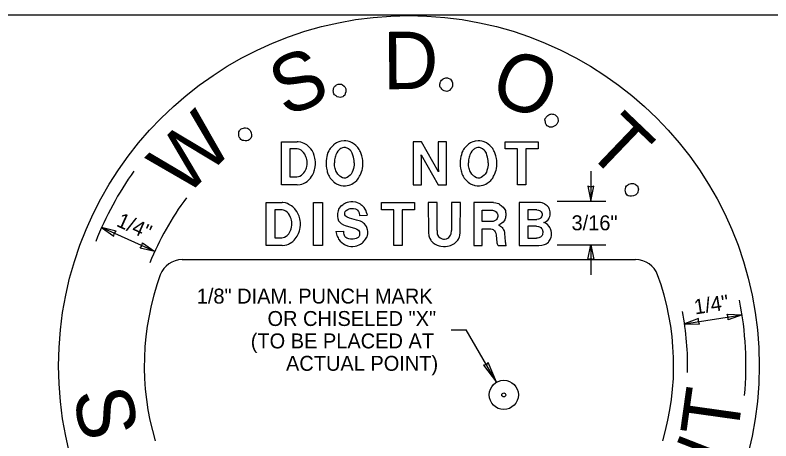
# Model space of a CAD drawing. Extents: x 99862 to 103151, y 100000 to 102076.
# Drawn here: x 100680 to 101489, y 101619 to 102076 of the extents above; entities that cross this region are included whole.
import ezdxf

# ---------------------------------------------------------------- set-up
doc = ezdxf.new("R2010")
doc.units = 0
for name, color, linetype in [('Level 1', 7, 'Continuous'), ('Level 10', 7, 'Continuous'), ('Level 15', 7, 'Continuous'), ('Level 18', 7, 'Continuous'), ('Level 20', 7, 'Continuous'), ('Level 6', 7, 'Continuous')]:
    doc.layers.add(name, color=color, linetype=linetype)

msp = doc.modelspace()

# ---------------------------------------------------------------- linework, layer by layer
at = {"layer": 'Level 1'}
msp.add_lwpolyline([(99862, 99999.5), (103151, 99999.5), (103151, 102075.5), (99862, 102075.5)], close=True, dxfattribs=at)
for radius, start, end in [(360.73, 144.68888, 158.35001), (298.33, 142.94323, 158.35001), (360.73, 354.93234, 11.21108), (298.33, 358.58596, 11.21108)]:
    msp.add_arc((101101.53, 101700), radius, start, end, dxfattribs=at)
at = {"layer": 'Level 10'}
for points in [[(101135.9, 101997.37), (101135.51, 101997.93), (101135.12, 101998.49), (101134.72, 101999.06), (101134.51, 102000.57), (101134.69, 102001.53), (101134.86, 102002.47), (101135.04, 102003.43), (101135.77, 102004.77), (101136.43, 102005.64), (101137.64, 102006.89), (101138.21, 102007.28), (101138.77, 102007.67), (101139.81, 102007.97), (101140.85, 102008.27), (101142.84, 102008.4), (101146.01, 102006.83), (101146.78, 102005.71), (101147.95, 102004.02), (101148.24, 102002.98), (101148.29, 102000.51), (101148.11, 101999.55), (101147.28, 101997.74), (101145.99, 101996), (101144.76, 101994.75), (101143.17, 101994.06), (101142.12, 101993.76), (101140.69, 101994.02), (101139.27, 101994.28), (101137.93, 101995.03), (101136.67, 101996.23), (101135.9, 101997.37)], [(101023.54, 101988.86), (101022.97, 101989.24), (101022.4, 101989.61), (101021.82, 101989.99), (101021.06, 101991.31), (101020.86, 101992.26), (101020.66, 101993.2), (101020.46, 101994.16), (101020.64, 101995.68), (101020.92, 101996.72), (101021.57, 101998.35), (101021.95, 101998.92), (101022.33, 101999.49), (101023.18, 102000.16), (101024.03, 102000.82), (101025.82, 102001.7), (101029.34, 102001.44), (101030.48, 102000.68), (101032.2, 101999.56), (101032.87, 101998.71), (101033.84, 101996.44), (101034.04, 101995.49), (101033.95, 101993.49), (101033.4, 101991.4), (101032.75, 101989.78), (101031.52, 101988.54), (101030.67, 101987.87), (101029.25, 101987.57), (101027.83, 101987.28), (101026.31, 101987.46), (101024.69, 101988.1), (101023.54, 101988.86)], [(101247.58, 101961.12), (101247.43, 101961.78), (101247.28, 101962.45), (101247.13, 101963.12), (101247.5, 101964.6), (101248.03, 101965.42), (101248.55, 101966.23), (101249.07, 101967.06), (101250.26, 101968.02), (101251.19, 101968.57), (101252.79, 101969.28), (101253.46, 101969.42), (101254.12, 101969.58), (101255.2, 101969.46), (101256.27, 101969.35), (101258.17, 101968.71), (101260.51, 101966.07), (101260.8, 101964.74), (101261.25, 101962.74), (101261.13, 101961.66), (101260.24, 101959.35), (101259.72, 101958.54), (101258.27, 101957.17), (101256.41, 101956.05), (101254.81, 101955.35), (101253.07, 101955.32), (101251.99, 101955.43), (101250.76, 101956.21), (101249.54, 101956.99), (101248.58, 101958.18), (101247.87, 101959.77), (101247.58, 101961.12)], [(100924.75, 101941.07), (100924.08, 101941.2), (100923.41, 101941.33), (100922.73, 101941.46), (100921.53, 101942.4), (100920.98, 101943.21), (100920.45, 101944.01), (100919.9, 101944.82), (100919.49, 101946.29), (100919.36, 101947.37), (100919.35, 101949.11), (100919.49, 101949.79), (100919.62, 101950.46), (100920.15, 101951.4), (100920.69, 101952.34), (100922.03, 101953.82), (100925.38, 101954.91), (100926.72, 101954.64), (100928.74, 101954.24), (100929.68, 101953.71), (100931.43, 101951.97), (100931.97, 101951.16), (100932.65, 101949.28), (100932.93, 101947.14), (100932.93, 101945.39), (100932.26, 101943.78), (100931.73, 101942.84), (100930.52, 101942.02), (100929.32, 101941.22), (100927.84, 101940.82), (100926.1, 101940.8), (100924.75, 101941.07)], [(101333.33, 101889.49), (101333.44, 101890.15), (101333.55, 101890.83), (101333.67, 101891.51), (101334.57, 101892.74), (101335.37, 101893.31), (101336.15, 101893.86), (101336.95, 101894.43), (101338.41, 101894.87), (101339.48, 101895.03), (101341.23, 101895.09), (101341.9, 101894.97), (101342.58, 101894.86), (101343.53, 101894.34), (101344.48, 101893.83), (101346, 101892.53), (101347.17, 101889.21), (101346.94, 101887.86), (101346.6, 101885.84), (101346.09, 101884.88), (101344.39, 101883.08), (101343.6, 101882.52), (101341.74, 101881.8), (101339.6, 101881.46), (101337.85, 101881.42), (101336.23, 101882.04), (101335.27, 101882.55), (101334.43, 101883.74), (101333.59, 101884.92), (101333.15, 101886.39), (101333.09, 101888.13), (101333.33, 101889.49)]]:
    msp.add_lwpolyline(points, dxfattribs=at)
at = {"layer": 'Level 15'}
for p, q in [((101296.23, 101908.37), (101296.23, 101876.37)), ((101260.23, 101876.37), (101312.23, 101876.37)), ((100829.4, 101822.25), (100772.48, 101847.82)), ((101260.23, 101829.44), (101312.23, 101829.44)), ((101296.23, 101829.44), (101296.23, 101797.44)), ((101396.45, 101744.97), (101458.15, 101754.38)), ((101146.74, 101738.51), (101162.74, 101738.51)), ((101195.24, 101682.22), (101162.74, 101738.51))]:
    msp.add_line(p, q, dxfattribs=at)
for points in [[(101296.23, 101876.37), (101299.32, 101892.1), (101296.23, 101891.37), (101293.15, 101892.1)], [(100772.48, 101847.82), (100785.56, 101838.57), (100786.16, 101841.68), (100788.08, 101844.19)], [(100829.4, 101822.25), (100813.79, 101825.88), (100815.72, 101828.4), (100816.32, 101831.51)], [(101296.23, 101829.44), (101299.32, 101813.72), (101296.23, 101814.45), (101293.15, 101813.72)], [(101396.45, 101744.97), (101412.46, 101744.29), (101411.28, 101747.23), (101411.53, 101750.39)], [(101458.15, 101754.38), (101443.07, 101748.96), (101443.32, 101752.12), (101442.14, 101755.06)], [(101195.25, 101682.22), (101186.42, 101703.48), (101184.36, 101701.07), (101181.25, 101700.5)]]:
    msp.add_lwpolyline(points, close=True, dxfattribs=at)
at = {"layer": 'Level 18'}
msp.add_line((100858.88, 101813.63), (101344.18, 101813.63), dxfattribs=at)
for centre, radius, start, end in [((100858.88, 101788.63), 25, 90, 159.93574), ((101344.18, 101788.63), 25, 20.06426, 90), ((101101.53, 101700), 283.33, 159.93574, 196.52295), ((101101.53, 101700), 283.33, 343.47705, 20.06426)]:
    msp.add_arc(centre, radius, start, end, dxfattribs=at)
at = {"layer": 'Level 20'}
for points in [[(100981.97, 101893.76), (100965.04, 101893.76), (100965.04, 101939.76), (100981.97, 101939.76)], [(100981.97, 101893.76), (100985.02, 101894.13), (100987.05, 101894.49), (100988.74, 101895.21), (100990.1, 101895.94), (100990.77, 101896.29), (100992.47, 101897.39), (100993.48, 101898.11), (100994.83, 101899.56), (100996.19, 101901.01), (100997.21, 101902.46), (100998.23, 101903.9), (100998.9, 101905.35), (100999.57, 101906.8), (101000.25, 101908.61), (101000.59, 101909.71), (101000.93, 101911.15), (101001.27, 101912.96), (101001.61, 101915.49), (101001.61, 101916.94), (101001.61, 101918.39), (101001.27, 101920.57), (101000.93, 101922.37), (101000.59, 101923.82), (101000.25, 101925.28), (100999.24, 101927.45), (100998.56, 101928.9), (100997.88, 101930.35), (100996.53, 101932.15), (100995.52, 101933.24), (100994.5, 101934.33), (100993.48, 101935.42), (100992.13, 101936.5), (100990.77, 101937.23), (100989.42, 101937.95), (100987.73, 101938.68), (100985.7, 101939.4), (100982.99, 101939.76), (100981.97, 101939.76)], [(101032.46, 101940.85), (101029.08, 101940.49), (101027.72, 101940.13), (101026.36, 101939.76), (101024.67, 101939.04), (101023.99, 101938.68), (101022.98, 101937.95), (101021.96, 101937.23), (101020.95, 101936.5), (101020.61, 101936.14), (101018.24, 101933.6), (101017.22, 101932.52), (101016.54, 101931.43), (101015.87, 101929.98), (101014.85, 101928.17), (101014.17, 101926), (101013.5, 101924.19), (101013.16, 101922.02), (101012.82, 101919.48), (101012.82, 101917.67), (101012.82, 101916.58)], [(101052.1, 101916.58), (101052.1, 101918.76), (101052.1, 101919.84), (101051.76, 101922.02), (101051.42, 101923.47), (101051.08, 101924.92), (101050.4, 101927.08), (101049.73, 101928.9), (101049.05, 101929.98), (101048.37, 101931.43), (101047.7, 101932.52), (101046.68, 101933.6), (101044.65, 101935.78), (101042.96, 101937.23), (101040.92, 101938.68), (101038.55, 101939.76), (101037.54, 101940.13), (101036.18, 101940.49), (101033.81, 101940.85), (101032.12, 101940.85)], [(101106.18, 101939.76), (101106.18, 101893.76), (101114.98, 101893.76), (101114.98, 101922.37), (101114.64, 101926), (101132.92, 101893.76), (101141.73, 101893.76), (101141.73, 101939.76), (101132.92, 101939.76), (101132.92, 101912.6), (101133.26, 101907.53), (101114.98, 101939.76), (101106.18, 101939.76)], [(101175.92, 101940.85), (101172.54, 101940.49), (101171.19, 101940.13), (101169.83, 101939.76), (101168.14, 101939.04), (101167.45, 101938.68), (101166.44, 101937.95), (101165.43, 101937.23), (101164.41, 101936.5), (101164.07, 101936.14), (101161.7, 101933.6), (101160.69, 101932.52), (101160, 101931.43), (101159.33, 101929.98), (101158.31, 101928.17), (101157.64, 101926), (101156.96, 101924.19), (101156.62, 101922.02), (101156.28, 101919.48), (101156.28, 101917.67), (101156.28, 101916.58)], [(101195.56, 101916.58), (101195.56, 101918.76), (101195.56, 101919.84), (101195.22, 101922.02), (101194.88, 101923.47), (101194.54, 101924.92), (101193.87, 101927.08), (101193.19, 101928.9), (101192.51, 101929.98), (101191.83, 101931.43), (101191.16, 101932.52), (101190.14, 101933.6), (101188.11, 101935.78), (101186.42, 101937.23), (101184.38, 101938.68), (101182.01, 101939.76), (101181, 101940.13), (101179.65, 101940.49), (101177.27, 101940.85), (101175.58, 101940.85)], [(101204.45, 101939.76), (101240, 101939.76), (101240, 101932.15), (101226.8, 101932.15), (101226.8, 101893.76), (101217.66, 101893.76), (101217.66, 101932.15), (101204.45, 101932.15), (101204.45, 101939.76)], [(100981.63, 101932.15), (100974.19, 101932.15), (100974.19, 101902.1), (100981.63, 101902.1)], [(100981.63, 101902.1), (100983.32, 101902.46), (100984.68, 101902.82), (100986.37, 101903.9), (100987.39, 101904.63), (100988.06, 101905.35), (100989.08, 101906.44), (100990.1, 101907.89), (100990.77, 101909.34), (100991.45, 101910.79), (100991.79, 101911.87), (100992.13, 101913.32), (100992.47, 101915.49), (100992.47, 101916.94), (100992.47, 101919.12), (100992.13, 101920.93), (100991.79, 101922.37), (100991.11, 101923.82), (100990.1, 101926.37), (100988.74, 101928.17), (100987.39, 101929.62), (100986.03, 101930.71), (100984.68, 101931.43), (100983.67, 101931.79), (100981.97, 101932.15), (100981.63, 101932.15)], [(101042.96, 101917.31), (101042.96, 101918.03), (101042.96, 101919.84), (101042.61, 101921.65), (101042.28, 101923.47), (101041.6, 101925.64), (101040.92, 101927.45), (101039.56, 101929.62), (101038.55, 101930.71), (101036.86, 101932.15), (101035.51, 101932.88), (101034.49, 101933.24), (101033.48, 101933.6), (101032.8, 101933.6), (101031.78, 101933.6), (101030.43, 101933.24), (101028.74, 101932.52), (101027.72, 101931.79), (101027.04, 101931.43), (101026.36, 101930.71), (101025.69, 101929.98), (101025.34, 101929.62), (101024.33, 101927.81), (101023.32, 101926), (101022.98, 101924.55), (101022.64, 101923.47), (101022.3, 101922.02), (101021.96, 101920.57), (101021.96, 101919.48), (101021.96, 101918.03), (101021.96, 101917.31)], [(101186.42, 101917.31), (101186.42, 101918.03), (101186.42, 101919.84), (101186.08, 101921.65), (101185.74, 101923.47), (101185.06, 101925.64), (101184.38, 101927.45), (101183.03, 101929.62), (101182.01, 101930.71), (101180.32, 101932.15), (101178.97, 101932.88), (101177.95, 101933.24), (101176.94, 101933.6), (101176.26, 101933.6), (101175.24, 101933.6), (101173.89, 101933.24), (101172.2, 101932.52), (101171.19, 101931.79), (101170.5, 101931.43), (101169.83, 101930.71), (101169.15, 101929.98), (101168.81, 101929.62), (101167.79, 101927.81), (101166.78, 101926), (101166.44, 101924.55), (101166.1, 101923.47), (101165.76, 101922.02), (101165.43, 101920.57), (101165.43, 101919.48), (101165.43, 101918.03), (101165.43, 101917.31)], [(101012.82, 101916.58), (101012.82, 101915.49), (101012.82, 101913.69), (101013.16, 101911.51), (101013.5, 101910.06), (101013.83, 101908.61), (101014.17, 101907.53), (101014.85, 101905.35), (101015.53, 101903.9), (101016.21, 101902.82), (101017.22, 101901.01), (101017.9, 101900.28), (101020.61, 101897.39), (101021.29, 101896.66), (101022.98, 101895.58), (101023.99, 101894.85), (101024.67, 101894.49), (101025.69, 101894.13), (101026.36, 101893.76), (101027.72, 101893.4), (101028.74, 101893.04), (101031.1, 101892.68), (101032.8, 101892.68), (101033.48, 101892.68), (101035.51, 101893.04), (101037.54, 101893.4), (101038.55, 101893.76), (101040.25, 101894.49), (101041.94, 101895.58), (101042.96, 101896.29), (101043.97, 101897.03), (101045.66, 101898.47), (101046.68, 101899.92), (101047.7, 101901.01), (101048.71, 101902.82), (101049.39, 101903.9), (101050.06, 101905.35), (101050.74, 101907.53), (101051.42, 101909.34), (101051.76, 101910.79), (101052.1, 101914.04), (101052.1, 101916.58)], [(101032.8, 101901.01), (101031.78, 101901.01), (101030.43, 101901.37), (101028.74, 101902.1), (101027.72, 101902.82), (101027.04, 101903.18), (101026.36, 101903.9), (101025.69, 101904.63), (101025.34, 101904.99), (101024.33, 101906.8), (101023.32, 101908.61), (101022.98, 101910.06), (101022.64, 101911.15), (101022.3, 101912.6), (101021.96, 101914.04), (101021.96, 101915.14), (101021.96, 101916.58), (101021.96, 101917.31)], [(101042.96, 101917.31), (101042.96, 101916.58), (101042.96, 101914.77), (101042.61, 101912.96), (101042.28, 101911.15), (101041.6, 101908.98), (101040.92, 101907.16), (101039.56, 101904.99), (101038.55, 101903.9), (101036.86, 101902.46), (101035.51, 101901.73), (101034.49, 101901.37), (101033.48, 101901.01), (101032.8, 101901.01)], [(101156.28, 101916.58), (101156.28, 101915.49), (101156.28, 101913.69), (101156.62, 101911.51), (101156.96, 101910.06), (101157.3, 101908.61), (101157.64, 101907.53), (101158.31, 101905.35), (101158.99, 101903.9), (101159.67, 101902.82), (101160.69, 101901.01), (101161.36, 101900.28), (101164.07, 101897.39), (101164.75, 101896.66), (101166.44, 101895.58), (101167.45, 101894.85), (101168.14, 101894.49), (101169.15, 101894.13), (101169.83, 101893.76), (101171.19, 101893.4), (101172.2, 101893.04), (101174.57, 101892.68), (101176.26, 101892.68), (101176.94, 101892.68), (101178.97, 101893.04), (101181, 101893.4), (101182.01, 101893.76), (101183.71, 101894.49), (101185.4, 101895.58), (101186.42, 101896.29), (101187.43, 101897.03), (101189.13, 101898.47), (101190.14, 101899.92), (101191.16, 101901.01), (101192.17, 101902.82), (101192.85, 101903.9), (101193.53, 101905.35), (101194.21, 101907.53), (101194.88, 101909.34), (101195.22, 101910.79), (101195.56, 101914.04), (101195.56, 101916.58)], [(101176.26, 101901.01), (101175.24, 101901.01), (101173.89, 101901.37), (101172.2, 101902.1), (101171.19, 101902.82), (101170.5, 101903.18), (101169.83, 101903.9), (101169.15, 101904.63), (101168.81, 101904.99), (101167.79, 101906.8), (101166.78, 101908.61), (101166.44, 101910.06), (101166.1, 101911.15), (101165.76, 101912.6), (101165.43, 101914.04), (101165.43, 101915.14), (101165.43, 101916.58), (101165.43, 101917.31)], [(101186.42, 101917.31), (101186.42, 101916.58), (101186.42, 101914.77), (101186.08, 101912.96), (101185.74, 101911.15), (101185.06, 101908.98), (101184.38, 101907.16), (101183.03, 101904.99), (101182.01, 101903.9), (101180.32, 101902.46), (101178.97, 101901.73), (101177.95, 101901.37), (101176.94, 101901.01), (101176.26, 101901.01)], [(100965.68, 101828.63), (100948.75, 101828.63), (100948.75, 101874.63), (100965.68, 101874.63)], [(100965.68, 101828.63), (100968.73, 101828.99), (100970.76, 101829.35), (100972.45, 101830.07), (100973.81, 101830.8), (100974.48, 101831.16), (100976.18, 101832.25), (100977.19, 101832.97), (100978.55, 101834.42), (100979.9, 101835.87), (100980.92, 101837.32), (100981.94, 101838.77), (100982.61, 101840.22), (100983.29, 101841.67), (100983.96, 101843.47), (100984.3, 101844.57), (100984.64, 101846.02), (100984.98, 101847.82), (100985.32, 101850.36), (100985.32, 101851.81), (100985.32, 101853.25), (100984.98, 101855.43), (100984.64, 101857.24), (100984.3, 101858.68), (100983.96, 101860.14), (100982.95, 101862.31), (100982.27, 101863.76), (100981.6, 101865.21), (100980.24, 101867.02), (100979.23, 101868.11), (100978.21, 101869.2), (100977.19, 101870.28), (100975.84, 101871.36), (100974.48, 101872.09), (100973.13, 101872.81), (100971.44, 101873.54), (100969.41, 101874.26), (100966.7, 101874.63), (100965.68, 101874.63)], [(100999.53, 101828.63), (100999.53, 101874.63), (101009.01, 101874.63), (101009.01, 101828.63), (100999.53, 101828.63)], [(101029.67, 101871.73), (101028.31, 101870.65), (101026.62, 101868.47), (101025.6, 101865.93), (101024.93, 101863.04), (101024.93, 101859.78), (101025.27, 101857.6), (101026.29, 101855.07), (101027.64, 101853.62), (101028.99, 101852.17), (101031.36, 101850.72), (101033.39, 101850), (101044.23, 101847.1), (101045.92, 101846.37), (101047.61, 101845.29)], [(101029.67, 101871.73), (101030.68, 101872.45), (101031.7, 101873.18), (101032.38, 101873.54), (101033.73, 101874.26), (101035.76, 101874.99), (101037.11, 101875.35), (101039.49, 101875.71), (101040.16, 101875.71), (101041.52, 101875.71), (101044.23, 101875.35), (101045.25, 101874.99), (101046.26, 101874.63), (101047.95, 101873.9), (101049.31, 101873.18), (101049.98, 101872.81), (101051, 101872.09)], [(101056.42, 101863.04), (101055.4, 101866.66), (101054.73, 101867.74), (101053.71, 101869.56), (101052.69, 101870.65), (101051, 101872.09)], [(101071.99, 101874.63), (101107.54, 101874.63), (101107.54, 101867.02), (101094.33, 101867.02), (101094.33, 101828.63), (101085.2, 101828.63), (101085.2, 101867.02), (101071.99, 101867.02), (101071.99, 101874.63)], [(101131.58, 101844.92), (101131.58, 101874.63), (101122.1, 101874.63), (101122.44, 101842.75)], [(101156.29, 101842.75), (101156.63, 101874.63), (101147.15, 101874.63), (101147.15, 101844.92)], [(101192.18, 101874.63), (101170.85, 101874.63), (101170.85, 101828.63), (101179.99, 101828.63), (101179.99, 101846.74), (101188.12, 101846.74)], [(101192.18, 101874.63), (101194.55, 101874.26), (101195.9, 101873.9), (101197.26, 101873.54), (101197.93, 101873.18), (101198.62, 101872.81), (101199.29, 101872.45), (101200.31, 101871.73), (101200.98, 101871), (101202.34, 101869.92), (101203.02, 101868.83), (101203.35, 101868.47), (101204.03, 101867.38), (101204.71, 101866.29), (101205.05, 101864.49), (101205.38, 101863.4), (101205.38, 101861.95), (101205.38, 101860.5), (101205.05, 101859.41), (101204.71, 101858.33), (101204.03, 101856.15), (101203.35, 101855.07), (101202.34, 101853.62), (101200.98, 101852.53), (101199.97, 101851.81), (101198.95, 101851.08), (101198.28, 101850.72), (101197.26, 101850.36), (101198.28, 101850), (101198.95, 101849.63), (101199.63, 101849.27), (101200.64, 101848.55), (101200.98, 101848.18), (101201.33, 101847.82), (101202, 101847.1), (101202.34, 101846.37), (101202.68, 101845.65), (101203.35, 101844.57), (101203.69, 101842.75), (101203.69, 101841.67), (101204.37, 101832.97), (101204.37, 101832.61), (101204.71, 101831.52), (101205.05, 101830.07), (101205.38, 101829.35), (101205.72, 101828.63)], [(101240.59, 101874.63), (101219.6, 101874.63), (101219.6, 101828.63), (101239.24, 101828.63)], [(101239.24, 101828.63), (101240.59, 101828.63), (101243.64, 101828.99), (101245.33, 101829.35), (101246.69, 101829.71), (101247.7, 101830.07), (101248.38, 101830.44), (101249.4, 101831.16), (101250.75, 101832.25), (101251.43, 101832.97), (101252.1, 101834.06), (101252.79, 101835.15), (101253.12, 101835.87), (101253.8, 101837.68), (101254.14, 101839.13), (101254.14, 101839.86), (101254.14, 101842.75), (101253.8, 101844.57), (101253.46, 101845.65), (101253.12, 101846.74), (101252.45, 101847.82), (101251.77, 101848.91), (101249.74, 101851.08), (101248.72, 101851.81), (101247.7, 101852.53), (101247.03, 101852.9), (101246.02, 101853.25), (101247.03, 101853.62), (101247.7, 101853.98), (101248.72, 101854.7), (101250.08, 101855.79), (101250.41, 101856.15), (101251.09, 101857.24), (101251.77, 101858.33), (101252.45, 101859.78), (101252.79, 101861.23), (101252.79, 101861.95), (101252.79, 101864.84), (101252.45, 101866.29), (101252.1, 101867.74), (101251.77, 101868.47), (101251.43, 101868.83), (101251.09, 101869.56), (101250.08, 101870.65), (101249.4, 101871.36), (101248.38, 101872.09), (101247.37, 101872.81), (101246.69, 101873.18), (101246.02, 101873.54), (101245, 101873.9), (101243.98, 101874.26), (101242.29, 101874.63), (101240.59, 101874.63)], [(100965.34, 101867.02), (100957.9, 101867.02), (100957.9, 101836.96), (100965.34, 101836.96)], [(100965.34, 101836.96), (100967.03, 101837.32), (100968.39, 101837.68), (100970.08, 101838.77), (100971.1, 101839.49), (100971.77, 101840.22), (100972.79, 101841.31), (100973.81, 101842.75), (100974.48, 101844.2), (100975.17, 101845.65), (100975.5, 101846.74), (100975.84, 101848.18), (100976.18, 101850.36), (100976.18, 101851.81), (100976.18, 101853.98), (100975.84, 101855.79), (100975.5, 101857.24), (100974.82, 101858.68), (100973.81, 101861.23), (100972.45, 101863.04), (100971.1, 101864.49), (100969.74, 101865.57), (100968.39, 101866.29), (100967.38, 101866.66), (100965.68, 101867.02), (100965.34, 101867.02)], [(101033.05, 101861.59), (101033.05, 101863.76), (101033.39, 101865.21), (101034.41, 101866.29), (101036.1, 101867.38), (101037.46, 101868.11), (101038.47, 101868.47), (101040.16, 101868.47), (101042.2, 101868.47), (101044.23, 101868.11), (101045.58, 101867.38), (101046.6, 101866.66), (101047.61, 101865.21), (101048.29, 101863.76), (101048.63, 101860.86)], [(101056.42, 101863.04), (101056.76, 101861.23)], [(101191.5, 101854.34), (101179.99, 101854.34), (101179.99, 101866.66), (101190.83, 101866.66)], [(101190.83, 101866.66), (101192.18, 101866.29), (101193.19, 101865.93), (101193.87, 101865.57), (101194.89, 101864.84), (101195.57, 101863.76), (101195.9, 101863.4), (101196.24, 101862.31), (101196.58, 101861.59), (101196.58, 101860.5), (101196.58, 101859.78), (101196.24, 101858.68), (101195.9, 101857.6), (101195.23, 101856.52), (101194.55, 101855.79), (101193.87, 101855.43), (101193.19, 101855.07), (101191.5, 101854.34), (101190.83, 101854.34)], [(101238.56, 101867.02), (101228.75, 101867.02), (101228.75, 101856.52), (101238.56, 101856.52)], [(101238.56, 101867.02), (101240.26, 101866.66), (101241.27, 101866.29), (101241.95, 101865.93), (101242.29, 101865.57), (101242.97, 101864.84), (101243.64, 101863.76), (101243.98, 101862.68), (101243.98, 101861.23), (101243.3, 101859.41), (101242.62, 101858.33), (101241.95, 101857.6), (101241.27, 101857.24), (101240.26, 101856.88), (101238.56, 101856.52)], [(101056.42, 101837.68), (101056.76, 101838.04), (101057.09, 101839.49), (101057.43, 101841.31), (101057.43, 101843.11), (101057.43, 101844.2), (101057.09, 101845.65), (101056.42, 101847.82), (101056.08, 101848.91), (101055.07, 101850.36), (101054.05, 101851.81), (101053.03, 101852.53), (101051.68, 101853.62), (101049.65, 101854.7), (101046.94, 101855.43), (101045.25, 101855.79), (101037.8, 101857.97), (101035.42, 101859.05), (101034.41, 101859.78), (101033.73, 101860.5), (101033.05, 101861.59)], [(101048.63, 101860.86), (101056.76, 101861.23)], [(101188.12, 101846.74), (101189.13, 101846.74), (101190.49, 101846.37), (101191.5, 101846.02), (101192.52, 101845.29), (101193.19, 101844.57), (101193.87, 101843.47), (101194.21, 101842.75), (101194.55, 101842.02), (101194.89, 101839.86), (101195.57, 101831.89), (101195.57, 101831.52), (101195.9, 101830.44), (101196.24, 101829.71), (101196.58, 101828.99), (101196.92, 101828.63)], [(101238.23, 101849.27), (101228.75, 101849.27), (101228.75, 101836.59), (101238.23, 101836.59)], [(101238.23, 101849.27), (101240.26, 101848.91), (101241.27, 101848.55), (101241.95, 101848.18), (101242.62, 101847.82), (101243.3, 101847.1), (101243.98, 101846.37), (101244.32, 101845.65), (101244.66, 101844.92), (101245, 101843.84), (101245, 101842.75), (101244.66, 101841.31), (101244.32, 101840.22), (101243.98, 101839.49), (101243.3, 101838.77), (101242.97, 101838.41), (101242.29, 101837.68), (101241.27, 101837.32), (101240.59, 101836.96), (101239.24, 101836.59), (101238.23, 101836.59)], [(101023.24, 101843.84), (101031.7, 101844.2)], [(101023.24, 101843.84), (101023.58, 101842.39), (101023.91, 101840.94), (101024.25, 101839.49), (101024.59, 101838.77), (101024.93, 101838.04), (101025.6, 101836.96), (101026.29, 101835.51), (101026.62, 101835.15), (101027.98, 101833.34), (101029.67, 101831.89), (101031.36, 101830.44), (101032.04, 101830.07), (101033.39, 101829.35), (101034.07, 101828.99), (101035.09, 101828.63), (101035.76, 101828.26), (101037.11, 101827.9), (101039.49, 101827.54), (101040.51, 101827.54), (101041.52, 101827.54), (101043.89, 101827.9), (101045.58, 101828.26), (101046.6, 101828.63), (101048.29, 101829.35), (101049.65, 101830.07), (101050.66, 101830.8), (101051.68, 101831.52), (101052.36, 101832.25), (101053.37, 101833.34), (101054.05, 101834.06), (101055.07, 101835.51), (101055.74, 101836.59), (101056.42, 101837.68)], [(101044.9, 101836.24), (101043.55, 101835.87), (101041.86, 101835.51), (101040.16, 101835.51), (101039.15, 101835.51), (101037.11, 101835.87), (101035.09, 101836.59), (101034.07, 101837.32), (101033.05, 101838.41), (101032.38, 101839.49), (101032.04, 101840.57), (101031.7, 101842.02), (101031.7, 101844.2)], [(101047.61, 101845.29), (101048.63, 101843.47), (101048.63, 101839.49), (101047.95, 101838.04), (101047.28, 101837.32), (101044.9, 101836.24)], [(101122.44, 101842.75), (101122.77, 101839.13), (101123.11, 101838.04), (101123.79, 101836.24), (101124.8, 101834.42), (101125.48, 101833.7), (101126.5, 101832.61), (101127.51, 101831.52), (101128.53, 101830.8), (101129.54, 101830.07), (101130.9, 101829.35), (101131.91, 101828.99), (101132.93, 101828.63), (101133.95, 101828.26), (101135.64, 101827.9), (101138.35, 101827.54), (101140.72, 101827.54), (101142.75, 101827.9), (101144.44, 101828.26), (101146.14, 101828.63), (101147.49, 101829.35), (101148.84, 101830.07), (101150.19, 101830.8), (101151.89, 101832.25), (101152.91, 101833.34), (101153.93, 101834.42), (101154.6, 101835.51), (101154.94, 101836.24), (101155.62, 101838.04), (101155.95, 101839.49), (101156.29, 101842.75)], [(101131.58, 101844.92), (101131.91, 101841.31), (101132.25, 101840.22), (101133.27, 101838.41), (101134.96, 101836.96), (101136.32, 101836.24), (101137, 101835.87), (101138.68, 101835.51), (101139.7, 101835.51), (101141.73, 101835.87), (101143.09, 101836.59), (101144.11, 101837.32), (101145.46, 101838.77), (101146.14, 101839.86), (101146.81, 101841.31), (101147.15, 101844.92)], [(101196.92, 101828.63), (101205.72, 101828.63)]]:
    msp.add_lwpolyline(points, dxfattribs=at)
at = {"layer": 'Level 6'}
for centre, radius in [((101101.53, 101700), 375), ((101203.06, 101668.69), 15.62), ((101203.06, 101668.69), 2.13)]:
    msp.add_circle(centre, radius, dxfattribs=at)

# ---------------------------------------------------------------- texts
at = {"layer": 'Level 10'}
for s, rotation, p in [('D', 0.5419, (101073.89, 101996.01)), ('S', 22.67359, (100969.17, 101965.78)), ('O', 338.41021, (101185.35, 101985.45)), ('W', 44.80529, (100861.15, 101878.8)), ('T', 316.27852, (101288.58, 101931.05)), ('T', 82.00798, (101452.69, 101620.79)), ('S', 281.09005, (100741.65, 101670.9)), ('N', 68.59815, (101429.27, 101553.05))]:
    msp.add_text(s, height=61.5, rotation=rotation, dxfattribs=at).set_placement(p)
at = {"layer": 'Level 20'}
for rotation, p in [(335.80872, (100787.41, 101849.89)), (8.66979, (101407.88, 101754.8))]:
    msp.add_text('1/4"', height=16, rotation=rotation, dxfattribs=at).set_placement(p)
for s, p in [('3/16"', (101275.57, 101845.02)), ('1/8" DIAM. PUNCH MARK', (100874.4, 101766.52)), ('OR CHISELED "X"', (100950.14, 101742.52)), ('(TO BE PLACED AT', (100932.2, 101718.52)), ('ACTUAL POINT)', (100969.93, 101694.52))]:
    msp.add_text(s, height=16, dxfattribs=at).set_placement(p)

doc.saveas('drawing.dxf')
